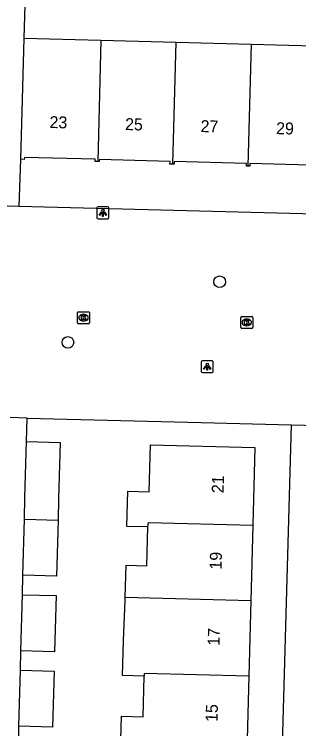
# Model space of a CAD drawing. Extents: x 162082 to 163393, y 388091 to 388632.
# Drawn here: x 162364.1 to 162387.9, y 388296.5 to 388356.4 of the extents above; entities that cross this region are included whole.
import ezdxf

# ---------------------------------------------------------------- set-up
doc = ezdxf.new("R2010")
doc.units = 0
for name, color, linetype in [('IMGEO_Boom', 7, 'Continuous'), ('IMGEO_Kolk', 7, 'Continuous'), ('IMGEO_Lichtpunt', 7, 'Continuous'), ('IMGEO_Muur', 7, 'Continuous'), ('IMGEO_Pand', 7, 'Continuous'), ('IMGEO_Pand_nummerreeks', 7, 'Continuous'), ('IMGEO_Voetpad_open', 7, 'Continuous')]:
    doc.layers.add(name, color=color, linetype=linetype)

msp = doc.modelspace()

# ---------------------------------------------------------------- linework, layer by layer
at = {"layer": 'IMGEO_Boom'}
for centre in [(162381.284, 388333.938), (162368.565, 388328.855)]:
    msp.add_circle(centre, 0.489, dxfattribs=at)
at = {"layer": 'IMGEO_Kolk'}
for p, q in [((162369.375, 388330.495), (162369.375, 388331.347)), ((162369.45, 388331.421), (162370.302, 388331.421)), ((162369.863, 388331.201), (162369.888, 388331.201)), ((162370.376, 388331.347), (162370.376, 388330.495)), ((162383.135, 388331.029), (162383.987, 388331.029)), ((162370.302, 388330.421), (162369.45, 388330.421)), ((162369.886, 388330.641), (162369.861, 388330.641)), ((162383.06, 388330.103), (162383.06, 388330.955)), ((162383.548, 388330.809), (162383.573, 388330.809)), ((162384.061, 388330.955), (162384.061, 388330.103)), ((162383.987, 388330.029), (162383.135, 388330.029)), ((162383.571, 388330.249), (162383.546, 388330.249))]:
    msp.add_line(p, q, dxfattribs=at)
for points in [[(162369.375, 388330.495), (162369.375, 388331.347)], [(162369.45, 388331.421), (162370.302, 388331.421)], [(162369.696, 388331.121), (162369.819, 388331.121), (162369.819, 388330.97), (162369.949, 388331.121), (162370.113, 388331.121), (162369.967, 388330.97), (162370.12, 388330.721), (162369.968, 388330.721), (162369.883, 388330.885), (162369.819, 388330.818), (162369.819, 388330.721), (162369.696, 388330.721), (162369.696, 388331.121)], [(162370.376, 388331.347), (162370.376, 388330.495)], [(162383.135, 388331.029), (162383.987, 388331.029)], [(162370.302, 388330.421), (162369.45, 388330.421)], [(162383.06, 388330.103), (162383.06, 388330.955)], [(162383.381, 388330.729), (162383.504, 388330.729), (162383.504, 388330.578), (162383.634, 388330.729), (162383.798, 388330.729), (162383.652, 388330.578), (162383.805, 388330.329), (162383.653, 388330.329), (162383.568, 388330.493), (162383.504, 388330.426), (162383.504, 388330.329), (162383.381, 388330.329), (162383.381, 388330.729)], [(162384.061, 388330.955), (162384.061, 388330.103)], [(162383.987, 388330.029), (162383.135, 388330.029)]]:
    msp.add_lwpolyline(points, dxfattribs=at)
for centre, start, end in [((162369.452, 388331.345), 91.55205, 178.44795), ((162369.452, 388331.345), 91.55205, 178.44795), ((162370.3, 388331.345), 1.55205, 88.44795), ((162370.3, 388331.345), 1.55205, 88.44795), ((162383.137, 388330.953), 91.55205, 178.44795), ((162383.137, 388330.953), 91.55205, 178.44795), ((162383.985, 388330.953), 1.55205, 88.44795), ((162383.985, 388330.953), 1.55205, 88.44795), ((162369.452, 388330.497), 181.55205, 268.44795), ((162369.452, 388330.497), 181.55205, 268.44795), ((162370.3, 388330.497), 271.55205, 358.44795), ((162370.3, 388330.497), 271.55205, 358.44795), ((162383.137, 388330.105), 181.55205, 268.44795), ((162383.137, 388330.105), 181.55205, 268.44795), ((162383.985, 388330.105), 271.55205, 358.44795), ((162383.985, 388330.105), 271.55205, 358.44795)]:
    msp.add_arc(centre, 0.0765, start, end, dxfattribs=at)
for centre, major_axis, ratio, start_param, end_param in [((162369.862, 388330.921), (-0.387, 0.002), 0.722429, 4.712389, 7.853982), ((162369.887, 388330.921), (-0.39, 0.002), 0.717154, 1.570796, 4.712389), ((162383.547, 388330.529), (-0.387, 0.002), 0.722429, 4.712389, 7.853982), ((162383.572, 388330.529), (-0.39, 0.002), 0.717154, 1.570796, 4.712389)]:
    msp.add_ellipse(centre, major_axis=major_axis, ratio=ratio, start_param=start_param, end_param=end_param, dxfattribs=at)
at = {"layer": 'IMGEO_Lichtpunt'}
for p, q in [((162371.003, 388340.126), (162371.003, 388339.319)), ((162371.003, 388340.126), (162371.003, 388339.319)), ((162371.905, 388340.221), (162371.097, 388340.221)), ((162371.905, 388340.221), (162371.097, 388340.221)), ((162371.999, 388339.319), (162371.999, 388340.126)), ((162371.999, 388339.319), (162371.999, 388340.126)), ((162371.097, 388339.225), (162371.905, 388339.225)), ((162371.097, 388339.225), (162371.905, 388339.225)), ((162379.744, 388327.221), (162379.744, 388326.414)), ((162379.744, 388327.221), (162379.744, 388326.414)), ((162380.646, 388327.316), (162379.838, 388327.316)), ((162380.646, 388327.316), (162379.838, 388327.316)), ((162380.74, 388326.414), (162380.74, 388327.221)), ((162380.74, 388326.414), (162380.74, 388327.221)), ((162379.838, 388326.32), (162380.646, 388326.32)), ((162379.838, 388326.32), (162380.646, 388326.32))]:
    msp.add_line(p, q, dxfattribs=at)
for points in [[(162371.377, 388339.79), (162371.416, 388339.762), (162371.228, 388339.5), (162371.19, 388339.527), (162371.377, 388339.79)], [(162371.479, 388339.742), (162371.526, 388339.742), (162371.526, 388339.42), (162371.479, 388339.42), (162371.479, 388339.742)], [(162371.589, 388339.762), (162371.627, 388339.789), (162371.814, 388339.527), (162371.775, 388339.499), (162371.589, 388339.762)], [(162380.118, 388326.885), (162380.157, 388326.857), (162379.969, 388326.595), (162379.931, 388326.622), (162380.118, 388326.885)], [(162380.22, 388326.837), (162380.267, 388326.837), (162380.267, 388326.515), (162380.22, 388326.515), (162380.22, 388326.837)], [(162380.33, 388326.857), (162380.368, 388326.884), (162380.555, 388326.622), (162380.516, 388326.594), (162380.33, 388326.857)]]:
    msp.add_lwpolyline(points, dxfattribs=at)
for centre in [(162371.502, 388339.924), (162380.243, 388327.019)]:
    msp.add_circle(centre, 0.0994, dxfattribs=at)
for centre, start, end in [((162371.097, 388340.126), 90, 180), ((162371.097, 388340.126), 90, 180), ((162371.905, 388340.126), 0, 90), ((162371.905, 388340.126), 0, 90), ((162371.097, 388339.319), 180, 270), ((162371.097, 388339.319), 180, 270), ((162371.905, 388339.319), 270, 0), ((162371.905, 388339.319), 270, 360), ((162379.838, 388327.221), 90, 180), ((162379.838, 388327.221), 90, 180), ((162380.646, 388327.221), 0, 90), ((162380.646, 388327.221), 0, 90), ((162379.838, 388326.414), 180, 270), ((162379.838, 388326.414), 180, 270), ((162380.646, 388326.414), 270, 0), ((162380.646, 388326.414), 270, 360)]:
    msp.add_arc(centre, 0.0946, start, end, dxfattribs=at)
at = {"layer": 'IMGEO_Muur'}
msp.add_lwpolyline([(162365.151, 388322.507), (162379.741, 388322.133)], dxfattribs=at)
at = {"layer": 'IMGEO_Pand'}
for points in [[(162364.883, 388354.378), (162364.742, 388349.211), (162364.606, 388344.212)], [(162364.883, 388354.378), (162371.339, 388354.202)], [(162371.339, 388354.202), (162371.066, 388344.014)], [(162371.339, 388354.202), (162377.636, 388354.031)], [(162377.362, 388343.8), (162377.636, 388354.031)], [(162377.636, 388354.031), (162383.933, 388353.86)], [(162383.933, 388353.86), (162383.659, 388343.634)], [(162383.933, 388353.86), (162390.231, 388353.688)], [(162371.066, 388344.014), (162370.841, 388344.02), (162370.846, 388344.209), (162364.915, 388344.37), (162364.911, 388344.204), (162364.606, 388344.212)], [(162377.362, 388343.8), (162377.123, 388343.807), (162377.13, 388344.032), (162371.203, 388344.192), (162371.198, 388344.01), (162371.066, 388344.014)], [(162383.659, 388343.634), (162383.538, 388343.637), (162383.544, 388343.855), (162377.472, 388344.02), (162377.466, 388343.797), (162377.362, 388343.8)], [(162389.958, 388343.465), (162389.831, 388343.469), (162389.837, 388343.683), (162383.825, 388343.847), (162383.819, 388343.629), (162383.659, 388343.634)], [(162364.922, 388314.032), (162364.964, 388315.844), (162365.096, 388320.545)], [(162365.096, 388320.545), (162367.919, 388320.466), (162367.787, 388315.765), (162367.745, 388313.953)], [(162375.273, 388313.376), (162373.503, 388313.424), (162373.582, 388316.379), (162375.383, 388316.33), (162375.489, 388320.272), (162384.238, 388320.037), (162384.063, 388313.523)], [(162364.79, 388309.331), (162364.922, 388314.032)], [(162367.745, 388313.953), (162367.613, 388309.252), (162364.79, 388309.331)], [(162364.922, 388314.032), (162367.745, 388313.953)], [(162375.273, 388313.376), (162375.315, 388313.759), (162384.063, 388313.523)], [(162373.364, 388307.471), (162373.436, 388310.166), (162375.185, 388310.119), (162375.273, 388313.376)], [(162384.063, 388313.523), (162383.893, 388307.187)], [(162364.752, 388307.696), (162367.575, 388307.617), (162367.443, 388302.916), (162364.62, 388302.995)], [(162364.62, 388302.995), (162364.752, 388307.696)], [(162374.971, 388300.877), (162373.155, 388300.926), (162373.234, 388303.864), (162373.356, 388307.192), (162373.364, 388307.471)], [(162383.893, 388307.187), (162373.364, 388307.471)], [(162383.893, 388307.187), (162383.723, 388300.852)], [(162364.582, 388301.361), (162367.405, 388301.282), (162367.273, 388296.581), (162364.45, 388296.66)], [(162364.45, 388296.66), (162364.582, 388301.361)], [(162383.723, 388300.852), (162374.972, 388301.088), (162374.971, 388300.877)], [(162374.782, 388294.537), (162372.969, 388294.585), (162373.047, 388297.509), (162374.879, 388297.46), (162374.971, 388300.877)], [(162383.723, 388300.852), (162383.552, 388294.516)]]:
    msp.add_lwpolyline(points, dxfattribs=at)
at = {"layer": 'IMGEO_Voetpad_open'}
for points in [[(162365.19, 388361.756), (162365.084, 388361.759), (162364.883, 388354.378)], [(162364.606, 388344.212), (162364.462, 388340.26)], [(162364.462, 388340.26), (162362.478, 388340.312)], [(162430.454, 388338.542), (162364.462, 388340.26)], [(162365.146, 388322.507), (162363.729, 388322.543)], [(162365.096, 388320.545), (162365.146, 388322.507)], [(162365.146, 388322.507), (162379.741, 388322.133), (162387.274, 388321.94)], [(162387.274, 388321.94), (162385.955, 388275.247)], [(162387.274, 388321.94), (162392.906, 388321.796)], [(162364.752, 388307.696), (162364.79, 388309.331)], [(162364.582, 388301.361), (162364.62, 388302.995)], [(162364.412, 388295.025), (162364.45, 388296.66)]]:
    msp.add_lwpolyline(points, dxfattribs=at)

# ---------------------------------------------------------------- texts
at = {"layer": 'IMGEO_Pand_nummerreeks'}
for s, rotation, p in [('23', 358.45693, (162367.017, 388346.834)), ('25', 358.45693, (162373.347, 388346.663)), ('27', 358.45693, (162379.677, 388346.493)), ('29', 358.45693, (162386.007, 388346.322)), ('21', 88.46105, (162381.614, 388316.198)), ('19', 88.46105, (162381.443, 388309.79)), ('17', 88.46105, (162381.271, 388303.404)), ('15', 88.46105, (162381.1, 388297.017))]:
    msp.add_text(s, height=1, rotation=rotation, dxfattribs=at).set_placement(p)

doc.saveas('drawing.dxf')
